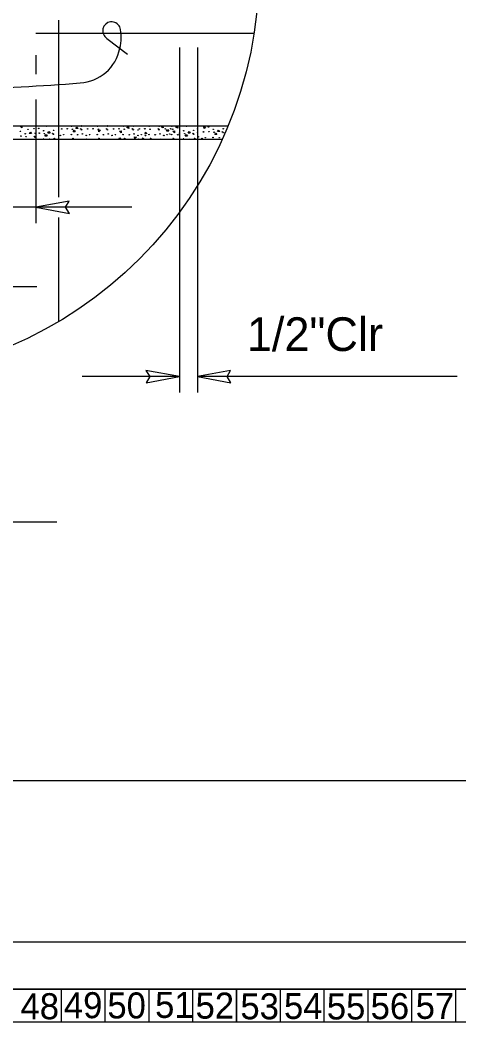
# Model space of a CAD drawing. Extents: x 0 to 2.83, y -0.03 to 1.83.
# Drawn here: x 0.9019 to 1.0716, y -0.0308 to 0.3561 of the extents above; entities that cross this region are included whole.
import ezdxf

# ---------------------------------------------------------------- set-up
doc = ezdxf.new("R2010")
doc.units = 0
for name, color, linetype in [('48', 7, 'Continuous'), ('49', 7, 'Continuous'), ('50', 7, 'Continuous'), ('51', 7, 'Continuous'), ('52', 7, 'Continuous'), ('53', 7, 'Continuous'), ('54', 7, 'Continuous'), ('55', 7, 'Continuous'), ('56', 7, 'Continuous'), ('57', 7, 'Continuous'), ('62', 7, 'Continuous'), ('63', 7, 'Continuous')]:
    doc.layers.add(name, color=color, linetype=linetype)

msp = doc.modelspace()

# ---------------------------------------------------------------- linework, layer by layer
at = {"layer": '50'}
for p, q in [((0.880179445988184, 0.3153115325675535), (0.9823069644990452, 0.3153115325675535)), ((0.880179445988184, 0.3101031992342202), (0.980048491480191, 0.3101031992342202))]:
    msp.add_line(p, q, dxfattribs=at)
at = {"layer": '51'}
for p, q in [((0.9168673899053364, 0.28769600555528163), (0.9168673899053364, 0.35611267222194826)), ((0.9922961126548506, 0.35089625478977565), (0.9079461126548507, 0.35089625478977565)), ((0.963479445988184, 0.3455712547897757), (0.963479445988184, 0.21229625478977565)), ((0.9704127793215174, 0.3455712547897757), (0.9704127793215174, 0.21229625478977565)), ((0.9079461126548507, 0.34260451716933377), (0.9079461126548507, 0.335263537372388)), ((0.9079461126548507, 0.32547556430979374), (0.9079461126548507, 0.27772125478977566)), ((0.9168673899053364, 0.2396960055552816), (0.9168673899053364, 0.2799056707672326))]:
    msp.add_line(p, q, dxfattribs=at)
at = {"layer": '55'}
for p, q in [((0.9354461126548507, 0.349004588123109), (0.9433961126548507, 0.342879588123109)), ((0.9079461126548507, 0.28382125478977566), (0.880179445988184, 0.28382125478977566)), ((0.9450570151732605, 0.28382125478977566), (0.9079461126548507, 0.28382125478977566)), ((0.9083794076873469, 0.253029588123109), (0.8714627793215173, 0.253029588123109)), ((0.963479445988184, 0.21842125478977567), (0.9259294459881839, 0.21842125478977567)), ((1.0709035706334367, 0.21842125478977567), (0.9704127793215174, 0.21842125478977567))]:
    msp.add_line(p, q, dxfattribs=at)
for points in [[(0.9025307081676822, 0.3145155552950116), (0.9020132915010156, 0.3150299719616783), (0.9026219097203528, 0.3153115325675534)], [(0.9026710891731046, 0.3153115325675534), (0.9025307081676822, 0.3145155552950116)], [(0.9079461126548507, 0.314298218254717), (0.9080042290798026, 0.31429295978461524), (0.9079461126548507, 0.31422370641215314)], [(0.922340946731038, 0.3129987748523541), (0.9227576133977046, 0.3135976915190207), (0.9231743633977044, 0.3129987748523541), (0.922340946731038, 0.3129987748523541)], [(0.9234508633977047, 0.31417335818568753), (0.9238675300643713, 0.3147722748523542), (0.9242842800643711, 0.31417335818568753), (0.9234508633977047, 0.31417335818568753)], [(0.9323656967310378, 0.3129955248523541), (0.9322367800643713, 0.31371360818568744), (0.9329550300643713, 0.3135848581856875), (0.9323656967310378, 0.3129955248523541)], [(0.9344953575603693, 0.3153115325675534), (0.9343880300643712, 0.3150831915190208), (0.9342562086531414, 0.3153115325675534)], [(0.9431356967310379, 0.31464460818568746), (0.9437960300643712, 0.3149549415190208), (0.9438574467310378, 0.3142279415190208), (0.9431356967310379, 0.31464460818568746)], [(0.9533628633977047, 0.3151201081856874), (0.9534960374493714, 0.3153115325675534)], [(0.954063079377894, 0.3153115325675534), (0.9541962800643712, 0.3151201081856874), (0.9533628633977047, 0.3151201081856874)], [(0.9571652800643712, 0.3144462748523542), (0.9565031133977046, 0.3147526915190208), (0.9570205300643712, 0.31526702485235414), (0.9571652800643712, 0.3144462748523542)], [(0.9585067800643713, 0.31321077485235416), (0.9589234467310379, 0.3138096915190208), (0.9593401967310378, 0.31321077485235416), (0.9585067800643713, 0.31321077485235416)], [(0.9620835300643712, 0.31471360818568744), (0.962743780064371, 0.3150239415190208), (0.962805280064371, 0.3142968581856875), (0.9620835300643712, 0.31471360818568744)], [(0.9730848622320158, 0.3142251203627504), (0.9728939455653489, 0.3149292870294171), (0.9736206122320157, 0.31486353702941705), (0.9730848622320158, 0.3142251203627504)], [(0.9782262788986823, 0.31303220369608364), (0.9786429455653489, 0.3136311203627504), (0.979059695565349, 0.31303220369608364), (0.9782262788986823, 0.31303220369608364)], [(0.905434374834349, 0.31226722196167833), (0.9058510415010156, 0.31286613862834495), (0.9062677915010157, 0.31226722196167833), (0.905434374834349, 0.31226722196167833)], [(0.9114999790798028, 0.31128704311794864), (0.9119166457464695, 0.31188595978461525), (0.9123333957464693, 0.31128704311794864), (0.9114999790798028, 0.31128704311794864)], [(0.9126098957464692, 0.31246162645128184), (0.913026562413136, 0.31306054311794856), (0.913443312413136, 0.31246162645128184), (0.9126098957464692, 0.31246162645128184)], [(0.9302807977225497, 0.3101031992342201), (0.9303124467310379, 0.3101486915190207), (0.9303441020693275, 0.3101031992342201)], [(0.9400790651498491, 0.3101031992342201), (0.9404331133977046, 0.3106121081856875), (0.9407872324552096, 0.3101031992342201)], [(0.940259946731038, 0.31315410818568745), (0.9409641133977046, 0.31334502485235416), (0.9408983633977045, 0.3126183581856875), (0.940259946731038, 0.31315410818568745)], [(0.9462610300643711, 0.31030285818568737), (0.9461321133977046, 0.3110209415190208), (0.9468503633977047, 0.3108921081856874), (0.9462610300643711, 0.31030285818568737)], [(0.9490674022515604, 0.3101031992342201), (0.9494193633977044, 0.3106091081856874), (0.9497713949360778, 0.3101031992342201)], [(0.9503205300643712, 0.31281019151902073), (0.9508380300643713, 0.3122956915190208), (0.9501756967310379, 0.3119892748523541), (0.9503205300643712, 0.31281019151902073)], [(0.956037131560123, 0.3101031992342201), (0.9563318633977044, 0.3101831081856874), (0.9563246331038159, 0.3101031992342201)], [(0.9608976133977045, 0.3131433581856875), (0.9616017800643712, 0.3133343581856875), (0.961536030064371, 0.31260769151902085), (0.9608976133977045, 0.3131433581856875)], [(0.9657048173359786, 0.31128704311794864), (0.9661214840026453, 0.31188595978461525), (0.9665382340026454, 0.31128704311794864), (0.9657048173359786, 0.31128704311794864)], [(0.9668147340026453, 0.31246162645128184), (0.967231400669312, 0.31306054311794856), (0.9676481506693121, 0.31246162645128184), (0.9668147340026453, 0.31246162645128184)], [(0.9771163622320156, 0.3118576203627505), (0.9775330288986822, 0.3124565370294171), (0.9779497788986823, 0.3118576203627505), (0.9771163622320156, 0.3118576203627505)]]:
    msp.add_lwpolyline(points, dxfattribs=at)
for points in [[(0.9079461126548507, 0.28382125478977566), (0.9209461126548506, 0.28144625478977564), (0.919429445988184, 0.28382125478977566), (0.9207961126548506, 0.28622125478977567)], [(0.963479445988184, 0.21842125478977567), (0.9504961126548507, 0.22079625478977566), (0.9519961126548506, 0.21842125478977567), (0.9506461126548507, 0.21602125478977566)], [(0.9704127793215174, 0.21842125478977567), (0.9834127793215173, 0.21604625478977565), (0.9818961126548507, 0.21842125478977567), (0.9832627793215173, 0.22082125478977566)]]:
    msp.add_lwpolyline(points, close=True, dxfattribs=at)
for centre, radius in [((0.8363386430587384, 0.3755134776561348), 0.1578956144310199), ((0.9049107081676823, 0.31393147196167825), 0.00010011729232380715), ((0.9072669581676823, 0.31414747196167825), 0.00010011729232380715), ((0.9091061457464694, 0.3142479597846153), 0.00010011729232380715), ((0.9109379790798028, 0.3133447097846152), 0.00010011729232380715), ((0.9119982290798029, 0.31507262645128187), 0.00010011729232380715), ((0.914806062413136, 0.3135410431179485), 0.00010011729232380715), ((0.9180032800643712, 0.3140746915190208), 0.00010011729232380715), ((0.9201041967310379, 0.31413360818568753), 0.00010011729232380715), ((0.9217789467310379, 0.3150564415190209), 0.00010011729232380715), ((0.9221323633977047, 0.31393727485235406), 0.00010011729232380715), ((0.9253328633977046, 0.3140746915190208), 0.00010011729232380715), ((0.925627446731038, 0.3137371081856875), 0.00010011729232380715), ((0.9280032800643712, 0.3140746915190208), 0.00010011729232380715), ((0.930104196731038, 0.31413360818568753), 0.00010011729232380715), ((0.9317789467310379, 0.3150564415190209), 0.00010011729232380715), ((0.9321323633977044, 0.31393727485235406), 0.00010011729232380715), ((0.9353328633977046, 0.3140746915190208), 0.00010011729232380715), ((0.935627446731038, 0.3137371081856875), 0.00010011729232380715), ((0.9380032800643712, 0.3140746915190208), 0.00010011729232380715), ((0.940104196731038, 0.31413360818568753), 0.00010011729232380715), ((0.9417789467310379, 0.3150564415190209), 0.00010011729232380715), ((0.9421323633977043, 0.31393727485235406), 0.00010011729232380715), ((0.9453328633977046, 0.3140746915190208), 0.00010011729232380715), ((0.945627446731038, 0.3137371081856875), 0.00010011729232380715), ((0.9474455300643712, 0.3136526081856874), 0.00010011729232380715), ((0.9480032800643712, 0.3140746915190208), 0.00010011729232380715), ((0.950104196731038, 0.31413360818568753), 0.00010011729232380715), ((0.9517789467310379, 0.3150564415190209), 0.00010011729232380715), ((0.9521323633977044, 0.31393727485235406), 0.00010011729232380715), ((0.9553328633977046, 0.3140746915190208), 0.00010011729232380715), ((0.9556274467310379, 0.3137371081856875), 0.00010011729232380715), ((0.9580032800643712, 0.3140746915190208), 0.00010011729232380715), ((0.960104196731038, 0.31413360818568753), 0.00010011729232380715), ((0.9605400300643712, 0.3150564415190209), 0.00010011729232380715), ((0.9608934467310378, 0.31393727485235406), 0.00010011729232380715), ((0.9651428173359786, 0.3133447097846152), 0.00010011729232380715), ((0.9662030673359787, 0.31507262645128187), 0.00010011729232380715), ((0.9690109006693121, 0.3135410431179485), 0.00010011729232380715), ((0.9747225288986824, 0.31481853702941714), 0.00010011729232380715), ((0.9765543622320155, 0.313915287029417), 0.00010011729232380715), ((0.980422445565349, 0.3141116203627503), 0.00010011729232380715), ((0.9020186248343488, 0.31310680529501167), 0.00010011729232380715), ((0.9021757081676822, 0.3112807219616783), 0.00010011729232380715), ((0.9038504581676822, 0.31220355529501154), 0.00010011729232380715), ((0.9042038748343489, 0.311084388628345), 0.00010011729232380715), ((0.9074043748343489, 0.31122180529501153), 0.00010011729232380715), ((0.9076989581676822, 0.31088422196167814), 0.00010011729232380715), ((0.9077185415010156, 0.31239988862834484), 0.00010011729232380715), ((0.9092632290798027, 0.31242187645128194), 0.00010011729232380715), ((0.9112913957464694, 0.3122255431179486), 0.00010011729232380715), ((0.9144918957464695, 0.3123629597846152), 0.00010011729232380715), ((0.9147864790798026, 0.3120253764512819), 0.00010011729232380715), ((0.9151202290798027, 0.3104349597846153), 0.00010011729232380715), ((0.9174534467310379, 0.31155760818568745), 0.00010011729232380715), ((0.9187297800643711, 0.3118521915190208), 0.00010011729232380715), ((0.9217003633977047, 0.31189144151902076), 0.00010011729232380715), ((0.9223286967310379, 0.3104384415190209), 0.00010011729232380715), ((0.9240958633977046, 0.3118129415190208), 0.00010011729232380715), ((0.9259611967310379, 0.3121466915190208), 0.00010011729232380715), ((0.9274534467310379, 0.31155760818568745), 0.00010011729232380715), ((0.9287297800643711, 0.3118521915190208), 0.00010011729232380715), ((0.9317003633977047, 0.31189144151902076), 0.00010011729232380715), ((0.9323286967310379, 0.3104384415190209), 0.00010011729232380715), ((0.9340958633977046, 0.3118129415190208), 0.00010011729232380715), ((0.935961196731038, 0.3121466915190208), 0.00010011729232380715), ((0.9374534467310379, 0.31155760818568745), 0.00010011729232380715), ((0.938729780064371, 0.3118521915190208), 0.00010011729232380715), ((0.9417003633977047, 0.31189144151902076), 0.00010011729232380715), ((0.9423286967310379, 0.3104384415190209), 0.00010011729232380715), ((0.9440958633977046, 0.3118129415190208), 0.00010011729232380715), ((0.9459611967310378, 0.3121466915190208), 0.00010011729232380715), ((0.9474534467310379, 0.31155760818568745), 0.00010011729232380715), ((0.948729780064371, 0.3118521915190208), 0.00010011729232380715), ((0.9503594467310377, 0.31146719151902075), 0.00010011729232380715), ((0.9517003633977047, 0.31189144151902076), 0.00010011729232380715), ((0.9523286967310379, 0.3104384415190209), 0.00010011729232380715), ((0.9540958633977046, 0.3118129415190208), 0.00010011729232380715), ((0.9559611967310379, 0.3121466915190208), 0.00010011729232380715), ((0.9574534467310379, 0.31155760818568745), 0.00010011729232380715), ((0.958729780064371, 0.3118521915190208), 0.00010011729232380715), ((0.9597485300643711, 0.3121146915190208), 0.00010011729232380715), ((0.9604614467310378, 0.31189144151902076), 0.00010011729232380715), ((0.9610897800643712, 0.3104384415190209), 0.00010011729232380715), ((0.9628569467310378, 0.3118129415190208), 0.00010011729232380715), ((0.9654962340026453, 0.3122255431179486), 0.00010011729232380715), ((0.9686967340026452, 0.3123629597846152), 0.00010011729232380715), ((0.9689913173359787, 0.3120253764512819), 0.00010011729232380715), ((0.9693250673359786, 0.3104349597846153), 0.00010011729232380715), ((0.9707366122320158, 0.31100553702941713), 0.00010011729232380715), ((0.9722288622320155, 0.3104164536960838), 0.00010011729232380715), ((0.972778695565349, 0.312933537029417), 0.00010011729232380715), ((0.973505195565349, 0.31071103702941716), 0.00010011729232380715), ((0.9748796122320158, 0.31299245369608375), 0.00010011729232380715), ((0.9764757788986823, 0.3107502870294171), 0.00010011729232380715), ((0.9769077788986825, 0.31279612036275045), 0.00010011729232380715), ((0.9788712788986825, 0.3106717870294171), 0.00010011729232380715), ((0.9801082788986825, 0.312933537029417), 0.00010011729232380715), ((0.9804028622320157, 0.31259595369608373), 0.00010011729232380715)]:
    msp.add_circle(centre, radius, dxfattribs=at)
for centre, radius, start, end in [((0.9372709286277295, 0.35195938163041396), 0.0034516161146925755, 25.24468333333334, 238.28830000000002), ((0.9265332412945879, 0.34931684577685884), 0.014469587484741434, 343.4589555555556, 16.521927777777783), ((0.9241245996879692, 0.34838486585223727), 0.016585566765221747, 273.25627222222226, 348.91487500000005), ((0.8312827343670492, 1.5619356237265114), 1.2336762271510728, 270.1320361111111, 274.35985833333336), ((0.9143544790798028, 0.31528862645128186), 0.00010011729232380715, 166.77399036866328, 13.226009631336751), ((0.9256470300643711, 0.3152527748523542), 0.00010011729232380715, 144.06346421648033, 35.936535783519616), ((0.9356470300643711, 0.3152527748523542), 0.00010011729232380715, 144.06346421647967, 35.9365357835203), ((0.9456470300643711, 0.3152527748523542), 0.00010011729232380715, 144.06346421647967, 35.9365357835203), ((0.9556470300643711, 0.3152527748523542), 0.00010011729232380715, 144.06346421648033, 35.936535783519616), ((0.9685593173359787, 0.31528862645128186), 0.00010011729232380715, 166.77399036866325, 13.226009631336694), ((0.9704224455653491, 0.3141116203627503), 0.00010011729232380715, 264.4595080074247, 95.54049199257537), ((0.9078888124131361, 0.31014045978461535), 0.00010011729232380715, 338.1505538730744, 55.08705789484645), ((0.9108593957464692, 0.3101797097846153), 0.00010011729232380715, 310.16331469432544, 229.83668530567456), ((0.9132548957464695, 0.3101012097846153), 0.00010011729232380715, 1.1386101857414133, 178.86138981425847), ((0.9176105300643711, 0.3100064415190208), 0.00010011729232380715, 75.11505006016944, 104.88494993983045), ((0.9276105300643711, 0.3100064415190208), 0.00010011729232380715, 75.11505006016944, 104.88494993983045), ((0.9376105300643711, 0.3100064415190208), 0.00010011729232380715, 75.11505006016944, 104.88494993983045), ((0.9476105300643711, 0.3100064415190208), 0.00010011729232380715, 75.11505006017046, 104.88494993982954), ((0.9576105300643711, 0.3100064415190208), 0.00010011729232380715, 75.11505006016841, 104.88494993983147), ((0.9634680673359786, 0.31242187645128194), 0.00010011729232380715, 276.52595068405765, 83.4740493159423), ((0.9650642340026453, 0.3101797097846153), 0.00010011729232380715, 310.1633146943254, 229.83668530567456), ((0.9674597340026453, 0.3101012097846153), 0.00010011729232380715, 1.1386101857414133, 178.8613898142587), ((0.9704028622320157, 0.31259595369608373), 0.00010011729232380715, 275.6847391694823, 84.31526083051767)]:
    msp.add_arc(centre, radius, start, end, dxfattribs=at)
at = {"layer": '57'}
msp.add_line((0.7877774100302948, 0.162304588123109), (0.9161127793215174, 0.162304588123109), dxfattribs=at)
at = {"layer": '62'}
for p, q in [((0.10494166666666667, -0.018041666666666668), (1.1717416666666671, -0.018041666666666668)), ((0.10495500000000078, -0.018096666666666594), (1.1717516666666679, -0.018096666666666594)), ((0.9177416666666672, -0.018041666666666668), (0.9177416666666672, -0.030741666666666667)), ((0.9177516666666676, -0.018096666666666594), (0.9177516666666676, -0.030796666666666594)), ((0.9346750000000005, -0.018041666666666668), (0.9346750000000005, -0.030741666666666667)), ((0.934685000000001, -0.018096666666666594), (0.934685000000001, -0.030796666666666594)), ((0.9516083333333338, -0.018041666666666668), (0.9516083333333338, -0.030741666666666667)), ((0.9516183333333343, -0.018096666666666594), (0.9516183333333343, -0.030796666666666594)), ((0.9685416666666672, -0.018041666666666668), (0.9685416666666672, -0.030741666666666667)), ((0.9685516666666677, -0.018096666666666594), (0.9685516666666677, -0.030796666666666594)), ((0.9854750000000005, -0.018041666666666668), (0.9854750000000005, -0.030741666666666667)), ((0.9854850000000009, -0.018096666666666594), (0.9854850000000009, -0.030796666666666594)), ((1.0024083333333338, -0.018041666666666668), (1.0024083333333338, -0.030741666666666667)), ((1.0024183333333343, -0.018096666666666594), (1.0024183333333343, -0.030796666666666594)), ((1.0193416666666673, -0.018041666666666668), (1.0193416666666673, -0.030741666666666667)), ((1.0193516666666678, -0.018096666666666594), (1.0193516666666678, -0.030796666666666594)), ((1.0362750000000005, -0.018041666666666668), (1.0362750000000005, -0.030741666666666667)), ((1.036285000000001, -0.018096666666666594), (1.036285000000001, -0.030796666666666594)), ((1.053208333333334, -0.018041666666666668), (1.053208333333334, -0.030741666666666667)), ((1.0532183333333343, -0.018096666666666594), (1.0532183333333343, -0.030796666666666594)), ((1.0701416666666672, -0.018041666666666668), (1.0701416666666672, -0.030741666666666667)), ((1.0701516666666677, -0.018096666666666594), (1.0701516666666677, -0.030796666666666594)), ((0.10494166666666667, -0.030741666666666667), (1.1717416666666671, -0.030741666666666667)), ((0.10495500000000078, -0.030796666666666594), (1.1717516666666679, -0.030796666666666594))]:
    msp.add_line(p, q, dxfattribs=at)
at = {"layer": '63'}
msp.add_line((2.833333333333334, 0), (0, 0), dxfattribs=at)
msp.add_lwpolyline([(2.729175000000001, 1.770775), (0.10417500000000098, 1.770775), (0.10417500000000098, 0.06244166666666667), (2.729175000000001, 0.06244166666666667)], close=True, dxfattribs=at)

# ---------------------------------------------------------------- texts
at = {"layer": '48'}
for height, p in [(0.00999995, (0.90205, -0.02969166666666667)), (0.009999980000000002, (0.9020616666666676, -0.02974999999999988))]:
    msp.add_text('48', height=height, dxfattribs=at).set_placement(p)
at = {"layer": '49'}
for height, p in [(0.00999995, (0.9188166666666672, -0.029291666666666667)), (0.009999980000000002, (0.918825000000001, -0.029346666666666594))]:
    msp.add_text('49', height=height, dxfattribs=at).set_placement(p)
at = {"layer": '50'}
for height, p in [(0.00999995, (0.9356250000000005, -0.029383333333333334)), (0.009999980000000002, (0.9356383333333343, -0.029436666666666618))]:
    msp.add_text('50', height=height, dxfattribs=at).set_placement(p)
at = {"layer": '51'}
for height, p in [(0.00999995, (0.9540666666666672, -0.029175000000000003)), (0.009999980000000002, (0.9540816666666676, -0.029233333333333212))]:
    msp.add_text('51', height=height, dxfattribs=at).set_placement(p)
at = {"layer": '52'}
for height, p in [(0.00999995, (0.9697166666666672, -0.029458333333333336)), (0.009999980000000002, (0.9697250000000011, -0.029516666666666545))]:
    msp.add_text('52', height=height, dxfattribs=at).set_placement(p)
at = {"layer": '53'}
for height, p in [(0.00999995, (0.9870500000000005, -0.0297)), (0.009999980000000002, (0.987065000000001, -0.02975666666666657))]:
    msp.add_text('53', height=height, dxfattribs=at).set_placement(p)
at = {"layer": '54'}
for height, p in [(0.00999995, (1.0039000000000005, -0.029583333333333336)), (0.009999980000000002, (1.003915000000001, -0.02963666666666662))]:
    msp.add_text('54', height=height, dxfattribs=at).set_placement(p)
at = {"layer": '55'}
for height, p in [(0.00999995, (1.0204666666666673, -0.029783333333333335)), (0.009999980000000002, (1.020475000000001, -0.029839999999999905))]:
    msp.add_text('55', height=height, dxfattribs=at).set_placement(p)
at = {"layer": '56'}
for height, p in [(0.00999995, (1.0373916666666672, -0.029666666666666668)), (0.009999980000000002, (1.037405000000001, -0.029723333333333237))]:
    msp.add_text('56', height=height, dxfattribs=at).set_placement(p)
at = {"layer": '57'}
for s, height, p in [('1/2"Clr', 0.013016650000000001, (0.9895461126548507, 0.22829568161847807)), ('57', 0.00999995, (1.0548166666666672, -0.02955)), ('57', 0.009999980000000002, (1.0548316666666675, -0.02960666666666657))]:
    msp.add_text(s, height=height, dxfattribs=at).set_placement(p)

doc.saveas('drawing.dxf')
